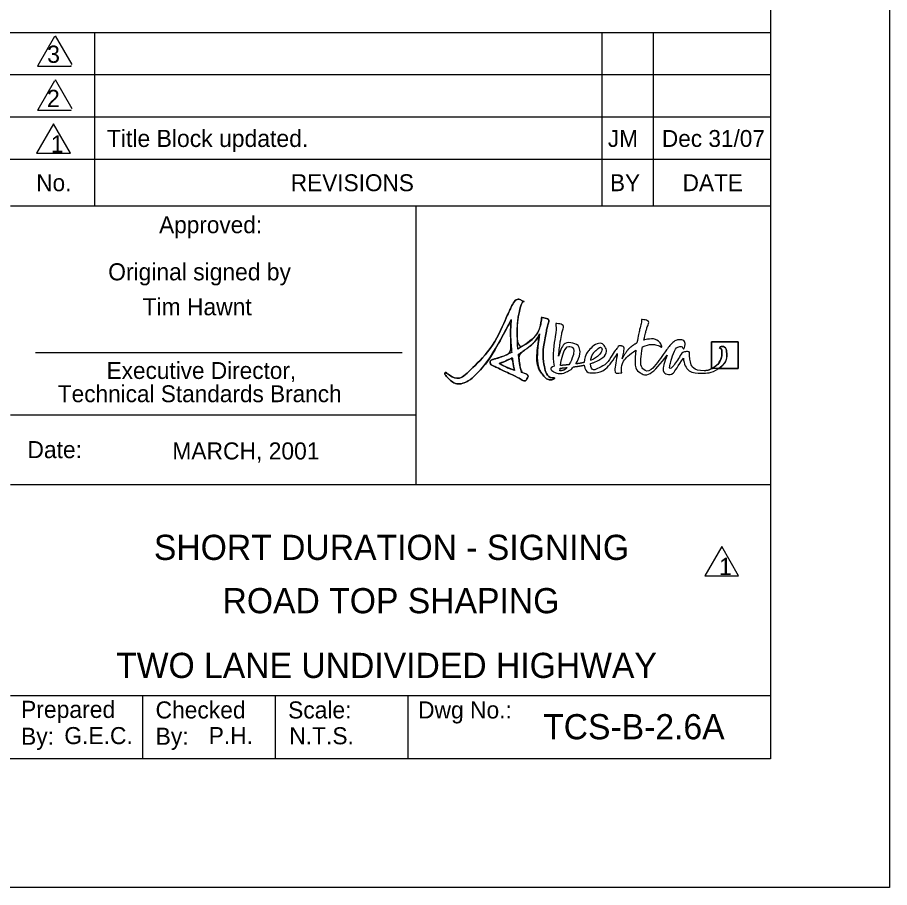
# Model space of a CAD drawing. Extents: x 1342 to 1558, y 178 to 457.
# Drawn here: x 1485 to 1558.3, y 177.9 to 251 of the extents above; entities that cross this region are included whole.
import ezdxf

# ---------------------------------------------------------------- set-up
doc = ezdxf.new("R2010")
doc.units = 0
for name, color, linetype in [('Level 1', 7, 'Continuous'), ('Level 10', 7, 'Continuous'), ('Level 2', 7, 'Continuous'), ('Level 22', 7, 'Continuous'), ('Level 44', 7, 'Continuous'), ('Level 45', 7, 'Continuous'), ('Level 53', 7, 'Continuous'), ('Level 60', 7, 'Continuous'), ('Level 63', 7, 'Continuous'), ('Level 7', 7, 'Continuous')]:
    doc.layers.add(name, color=color, linetype=linetype)

msp = doc.modelspace()

# ---------------------------------------------------------------- linework, layer by layer
at = {"layer": 'Level 1'}
for p, q in [((1518.49, 235.196), (1518.49, 211.787)), ((1484.439, 217.639), (1518.49, 217.639)), ((1484.439, 211.787), (1548.282, 211.787)), ((1484.439, 194.053), (1548.282, 194.053)), ((1495.57, 188.732), (1495.57, 194.053)), ((1506.7, 188.732), (1506.7, 194.053)), ((1517.83, 194.053), (1517.83, 188.732))]:
    msp.add_line(p, q, dxfattribs=at)
msp.add_lwpolyline([(1544.184, 206.591), (1542.765, 204.121), (1545.603, 204.121)], close=True, dxfattribs=at)
at = {"layer": 'Level 10'}
msp.add_line((1548.282, 188.732), (1548.282, 188.732), dxfattribs=at)
msp.add_line((1548.282, 188.732), (1548.282, 188.732), dxfattribs=at)
msp.add_line((1548.282, 188.732), (1548.282, 188.732), dxfattribs=at)
at = {"layer": 'Level 2'}
msp.add_line((1518.49, 235.196), (1518.49, 235.196), dxfattribs=at)
at = {"layer": 'Level 22'}
msp.add_line((1499.902, 188.732), (1499.902, 188.732), dxfattribs=at)
at = {"layer": 'Level 44'}
for p, q in [((1548.312, 249.746), (1484.432, 249.746)), ((1548.312, 246.197), (1484.432, 246.197)), ((1548.312, 242.648), (1484.432, 242.648)), ((1548.312, 239.1), (1484.432, 239.1)), ((1484.439, 235.196), (1548.312, 235.196))]:
    msp.add_line(p, q, dxfattribs=at)
msp.add_lwpolyline([(1488.059, 242.081), (1486.64, 239.611), (1489.478, 239.611)], close=True, dxfattribs=at)
at = {"layer": 'Level 45'}
msp.add_line((1518.505, 235.196), (1518.505, 235.196), dxfattribs=at)
at = {"layer": 'Level 53'}
msp.add_line((1543.939, 221.545), (1543.389, 221.545), dxfattribs=at)
msp.add_lwpolyline([(1543.939, 221.545), (1545.555, 221.545), (1545.555, 223.775), (1543.325, 223.775), (1543.325, 221.545), (1543.389, 221.545)], dxfattribs=at)
for points, degree in [([(1529.954, 220.736), (1529.714, 220.771), (1529.4, 221.098), (1529.305, 221.635), (1529.133, 222.601), (1529.235, 223.555), (1529.519, 224.976), (1529.573, 225.245), (1529.756, 225.711), (1529.173, 225.8), (1528.987, 225.829), (1529.083, 225.738), (1529.031, 225.492), (1528.807, 224.433), (1527.941, 223.671), (1527.072, 223.159), (1526.981, 224.371), (1527.019, 225.717), (1527.247, 226.542), (1527.439, 227.238), (1527.668, 227.11), (1527.384, 227.256), (1527.085, 227.411), (1526.764, 227.207), (1526.505, 226.688), (1526.245, 226.17), (1525.048, 223.354), (1523.137, 221.453), (1522.159, 220.481), (1521.274, 220.981), (1521.097, 221.131), (1520.953, 221.253), (1520.899, 221.065), (1521.078, 220.872), (1521.869, 220.02), (1523.025, 220.509), (1523.446, 220.929), (1524.608, 222.092), (1525.96, 224.594), (1526.507, 225.656), (1526.457, 225.058), (1526.44, 224.055), (1526.551, 222.88), (1525.959, 222.592), (1525.429, 222.422), (1525.179, 222.357), (1524.908, 222.286), (1524.74, 222.175), (1524.735, 222.049), (1524.729, 221.912), (1524.912, 221.796), (1525.175, 221.671), (1525.643, 221.449), (1527.015, 220.801), (1527.353, 220.604), (1527.642, 220.436), (1527.784, 220.567), (1527.87, 220.748), (1527.982, 220.985), (1527.674, 221.121), (1527.377, 221.21), (1527.262, 221.608), (1527.171, 222.144), (1527.11, 222.733), (1527.807, 223.163), (1528.494, 223.734), (1528.89, 224.449), (1528.79, 223.852), (1528.535, 221.821), (1529.175, 220.963), (1529.317, 220.774), (1529.629, 220.567), (1529.933, 220.597), (1530.076, 220.612), (1530.149, 220.706), (1530.134, 220.735), (1530.12, 220.765), (1530.038, 220.723), (1529.954, 220.736)], 3), ([(1527.072, 223.159), (1526.981, 224.371), (1527.019, 225.717), (1527.247, 226.542), (1527.439, 227.238), (1527.668, 227.11), (1527.384, 227.256), (1527.085, 227.411), (1526.764, 227.207), (1526.505, 226.688), (1526.245, 226.17), (1525.048, 223.354), (1523.137, 221.453), (1522.159, 220.481), (1521.274, 220.981), (1521.097, 221.131), (1520.953, 221.253), (1520.899, 221.065), (1521.078, 220.872), (1521.869, 220.02), (1523.025, 220.509), (1523.446, 220.929), (1524.608, 222.092), (1525.96, 224.594), (1526.507, 225.656)], 3), ([(1526.507, 225.656), (1526.457, 225.058), (1526.44, 224.055), (1526.551, 222.88)], 2), ([(1529.954, 220.736), (1529.714, 220.771), (1529.4, 221.098), (1529.305, 221.635), (1529.133, 222.601), (1529.235, 223.555), (1529.519, 224.976), (1529.573, 225.245), (1529.756, 225.711), (1529.173, 225.8), (1528.987, 225.829), (1529.083, 225.738), (1529.031, 225.492), (1528.807, 224.433), (1527.941, 223.671), (1527.072, 223.159)], 3), ([(1537.645, 223.918), (1537.71, 224.216), (1537.785, 224.518), (1537.867, 224.812), (1537.942, 225.081), (1538.163, 225.546), (1537.587, 225.636), (1537.404, 225.665), (1537.481, 225.576), (1537.421, 225.327), (1537.309, 224.87), (1537.169, 224.277), (1537.067, 223.682)], 3), ([(1530.49, 222.578), (1530.537, 223.146), (1530.628, 223.839), (1530.756, 224.481), (1530.81, 224.75), (1530.994, 225.216), (1530.41, 225.306), (1530.224, 225.334), (1530.253, 225.248), (1530.268, 224.997), (1530.289, 224.66), (1529.916, 222.621), (1530.111, 221.725)], 3), ([(1527.11, 222.733), (1527.807, 223.163), (1528.494, 223.734), (1528.89, 224.449)], 2), ([(1528.89, 224.449), (1528.79, 223.852), (1528.535, 221.821), (1529.175, 220.963), (1529.317, 220.774), (1529.629, 220.567), (1529.933, 220.597), (1530.076, 220.612), (1530.149, 220.706), (1530.134, 220.735), (1530.12, 220.765), (1530.038, 220.723), (1529.954, 220.736)], 3), ([(1531.928, 221.916), (1532.343, 222.589), (1532.307, 223.499), (1531.701, 223.652), (1530.997, 223.83), (1530.641, 223.146), (1530.49, 222.578)], 3), ([(1530.641, 221.787), (1530.735, 222.503), (1531.108, 223.498), (1531.572, 223.338), (1531.839, 223.245), (1531.698, 222.407), (1531.356, 221.85)], 3), ([(1533.154, 221.939), (1533.251, 221.968), (1533.337, 221.999), (1533.409, 222.031), (1534.292, 222.422), (1534.596, 223.012), (1534.371, 223.372), (1534.158, 223.713), (1533.55, 223.61), (1533.069, 223.103), (1532.832, 222.854), (1532.65, 222.425), (1532.628, 222.034)], 3), ([(1535.829, 222.353), (1535.885, 222.63), (1535.972, 222.936), (1535.978, 223.142), (1535.984, 223.359), (1535.835, 223.408), (1535.777, 223.424), (1535.651, 223.461), (1535.498, 223.398), (1535.347, 223.185), (1534.994, 222.688), (1534.547, 221.9), (1533.867, 221.57), (1533.38, 221.333), (1533.166, 221.572), (1533.154, 221.939)], 3), ([(1537.067, 223.682), (1536.593, 223.409), (1536.152, 222.953), (1535.829, 222.353)], 2), ([(1542.7, 221.347), (1541.784, 221.347), (1541.548, 222.059), (1541.504, 222.411), (1541.474, 222.645), (1541.525, 222.984), (1541.12, 222.939), (1540.837, 222.907), (1540.581, 222.356), (1540.223, 221.892), (1539.914, 221.493), (1539.777, 221.531), (1539.848, 221.873), (1539.938, 222.302), (1540.295, 223.307), (1540.704, 223.38), (1540.893, 223.414), (1540.961, 223.082), (1541.048, 223.29), (1541.135, 223.498), (1541.055, 223.948), (1540.632, 223.948), (1540.335, 223.948), (1539.98, 223.634), (1539.688, 223.276), (1539.434, 222.964), (1538.148, 221.072), (1537.609, 221.48), (1537.357, 221.671), (1537.378, 222.448), (1537.536, 223.365)], 3), ([(1537.536, 223.365), (1538.176, 223.611), (1538.708, 223.531), (1539.009, 223.386), (1539.157, 223.315), (1539.178, 223.325), (1539.114, 223.489), (1539.021, 223.729), (1538.506, 224.104), (1537.702, 223.932), (1537.683, 223.928), (1537.664, 223.923), (1537.645, 223.918)], 3), ([(1543.325, 223.775), (1543.325, 223.775), (1543.325, 221.545), (1543.325, 221.545), (1543.325, 221.545), (1543.389, 221.545), (1543.389, 221.545), (1543.873, 221.835), (1544.199, 222.389), (1544.198, 222.845), (1544.198, 223.239), (1543.989, 223.219), (1544.012, 223.274), (1544.08, 223.432), (1544.573, 223.342), (1544.602, 222.786), (1544.626, 222.314), (1544.379, 221.857), (1543.939, 221.545), (1543.939, 221.545), (1545.555, 221.545), (1545.555, 221.545), (1545.555, 221.545), (1545.555, 223.775), (1545.555, 223.775), (1545.555, 223.775), (1543.325, 223.775), (1543.325, 223.775)], 3), ([(1526.551, 222.88), (1525.959, 222.592), (1525.429, 222.422), (1525.179, 222.357), (1524.908, 222.286), (1524.74, 222.175), (1524.735, 222.049), (1524.729, 221.912), (1524.912, 221.796), (1525.175, 221.671), (1525.643, 221.449), (1527.015, 220.801), (1527.353, 220.604), (1527.642, 220.436), (1527.784, 220.567), (1527.87, 220.748), (1527.982, 220.985), (1527.674, 221.121), (1527.377, 221.21)], 3), ([(1527.377, 221.21), (1527.262, 221.608), (1527.171, 222.144), (1527.11, 222.733)], 2), ([(1532.635, 221.813), (1532.683, 221.421), (1532.94, 221.12), (1533.535, 221.175), (1534.381, 221.254), (1535.133, 222.293), (1535.417, 222.794)], 3), ([(1533.627, 223.058), (1533.923, 223.333), (1534.069, 223.313), (1534.108, 223.239), (1534.192, 223.08), (1533.844, 222.517), (1533.177, 222.209)], 3), ([(1533.177, 222.209), (1533.234, 222.512), (1533.394, 222.842), (1533.627, 223.058)], 2), ([(1535.417, 222.794), (1535.365, 222.257), (1535.016, 221.085), (1535.612, 221.145), (1535.845, 221.169), (1535.744, 221.206), (1535.758, 221.408), (1535.809, 222.114), (1536.398, 222.713), (1536.98, 223.08)], 3), ([(1536.98, 223.08), (1536.879, 222.215), (1536.914, 221.442), (1537.306, 221.197), (1538.028, 220.745), (1539.051, 221.934), (1539.614, 222.661)], 3), ([(1543.389, 221.545), (1543.873, 221.835), (1544.199, 222.389), (1544.198, 222.845), (1544.198, 223.239), (1543.989, 223.219), (1544.012, 223.274), (1544.08, 223.432), (1544.573, 223.342), (1544.602, 222.786), (1544.626, 222.314), (1544.379, 221.857), (1543.939, 221.545)], 3), ([(1525.482, 221.948), (1525.791, 222.061), (1526.184, 222.226), (1526.598, 222.443)], 2), ([(1525.482, 221.948), (1525.791, 222.061), (1526.184, 222.226), (1526.598, 222.443), (1526.654, 221.97), (1526.714, 221.627), (1526.782, 221.374), (1526.479, 221.483), (1526.046, 221.66), (1525.482, 221.948)], 3), ([(1526.782, 221.374), (1526.479, 221.483), (1526.046, 221.66), (1525.482, 221.948)], 2), ([(1526.598, 222.443), (1526.654, 221.97), (1526.714, 221.627), (1526.782, 221.374)], 2), ([(1532.628, 222.034), (1532.425, 221.99), (1532.19, 221.951), (1531.928, 221.916)], 2), ([(1539.614, 222.661), (1539.327, 222.015), (1539.165, 221.188), (1539.595, 221.062), (1540.1, 220.914), (1540.498, 221.752), (1540.964, 222.393)], 3), ([(1540.964, 222.393), (1541.018, 221.933), (1541.325, 221.14), (1542.561, 221.14), (1543.117, 221.14), (1543.589, 221.297), (1543.939, 221.545)], 3), ([(1530.111, 221.725), (1529.86, 221.643), (1529.758, 221.455), (1530.081, 221.255), (1530.303, 221.118), (1530.793, 221.072), (1531.288, 221.316), (1531.466, 221.404), (1531.62, 221.527), (1531.748, 221.672)], 3), ([(1530.566, 221.355), (1530.598, 221.382), (1530.617, 221.422), (1530.617, 221.47), (1530.618, 221.5), (1530.618, 221.532), (1530.62, 221.565)], 3), ([(1530.767, 221.356), (1530.686, 221.344), (1530.619, 221.345), (1530.566, 221.355)], 2), ([(1530.62, 221.565), (1530.746, 221.571), (1530.942, 221.585), (1531.177, 221.608)], 2), ([(1531.356, 221.85), (1531.131, 221.827), (1530.892, 221.806), (1530.641, 221.787)], 2), ([(1531.177, 221.608), (1531.054, 221.473), (1530.916, 221.379), (1530.767, 221.356)], 2), ([(1531.748, 221.672), (1532.043, 221.71), (1532.352, 221.757), (1532.635, 221.813)], 2), ([(1543.389, 221.545), (1543.183, 221.423), (1542.949, 221.347), (1542.7, 221.347)], 2)]:
    msp.add_open_spline(points, degree=degree, dxfattribs=at)
at = {"layer": 'Level 60'}
for p, q in [((1548.282, 188.732), (1548.282, 188.732)), ((1558.282, 177.923), (1558.282, 177.923))]:
    msp.add_line(p, q, dxfattribs=at)
for points in [[(1342.282, 456.923), (1558.282, 456.923), (1558.282, 177.923), (1342.282, 177.923)], [(1361.408, 446.114), (1548.282, 446.114), (1548.282, 188.732), (1361.408, 188.732)]]:
    msp.add_lwpolyline(points, close=True, dxfattribs=at)
at = {"layer": 'Level 63'}
for p, q in [((1491.529, 243.274), (1491.529, 249.746)), ((1534.118, 249.746), (1534.118, 235.196)), ((1538.429, 249.746), (1538.429, 235.196)), ((1491.529, 235.196), (1491.529, 243.274))]:
    msp.add_line(p, q, dxfattribs=at)
for points in [[(1488.138, 249.415), (1486.745, 246.99)], [(1489.62, 247.067), (1488.226, 249.492)], [(1486.745, 246.99), (1486.719, 246.945), (1489.558, 246.945), (1489.532, 246.99)], [(1488.138, 245.699), (1486.745, 243.274)], [(1489.62, 243.351), (1488.226, 245.776)], [(1486.745, 243.274), (1486.719, 243.229), (1489.558, 243.229), (1489.532, 243.274)]]:
    msp.add_lwpolyline(points, dxfattribs=at)
at = {"layer": 'Level 7'}
msp.add_line((1486.547, 222.882), (1517.348, 222.882), dxfattribs=at)

# ---------------------------------------------------------------- texts
at = {"layer": 'Level 1'}
for s, height, p in [('Title Block updated. ', 1.44, (1492.548, 240.144)), ('Date:', 1.4329, (1485.873, 214.001)), ('1', 1.448, (1543.957, 204.178)), ('Prepared', 1.44, (1485.327, 192.173)), ('Checked', 1.4329, (1496.633, 192.131)), ('Scale:', 1.4329, (1507.763, 192.131)), ('Dwg No.:', 1.4329, (1518.681, 192.131)), ('By:', 1.44, (1485.327, 189.917)), ('By:', 1.44, (1496.633, 189.917)), ('    N.T.S.   ', 1.43292, (1505.734, 189.96))]:
    msp.add_text(s, height=height, rotation=360, dxfattribs=at).set_placement(p)
at = {"layer": 'Level 10'}
for s, height, p in [('SHORT DURATION - SIGNING', 2.115, (1496.493, 205.449)), ('ROAD TOP SHAPING', 2.11517, (1502.259, 200.97)), ('TWO LANE UNDIVIDED HIGHWAY', 2.11517, (1493.323, 195.532))]:
    msp.add_text(s, height=height, rotation=359.99999, dxfattribs=at).set_placement(p)
at = {"layer": 'Level 44'}
for s, height, p in [('3', 1.448, (1487.528, 247.214)), ('2', 1.448, (1487.511, 243.498)), ('1', 1.448, (1487.832, 239.668)), ('JM', 1.4189, (1534.622, 240.149)), ('Dec 31/07', 1.419, (1539.163, 240.149)), ('No.', 1.4195, (1486.611, 236.431)), ('REVISIONS', 1.4195, (1507.994, 236.431)), ('BY', 1.4195, (1534.8, 236.431)), ('DATE', 1.4194, (1540.902, 236.431))]:
    msp.add_text(s, height=height, rotation=360, dxfattribs=at).set_placement(p)
at = {"layer": 'Level 60'}
for s, height, p in [('MARCH, 2001', 1.434, (1498.039, 213.89)), ('TCS-B-2.6A', 2.115, (1529.185, 190.38))]:
    msp.add_text(s, height=height, dxfattribs=at).set_placement(p)
for s, p in [('G.E.C.', (1488.97, 189.974)), ('P.H.', (1501.092, 189.974))]:
    msp.add_text(s, height=1.433, rotation=360, dxfattribs=at).set_placement(p)
at = {"layer": 'Level 7'}
for s, height, p in [('Approved:', 1.4187, (1496.933, 232.902)), ('Original signed by', 1.434, (1492.655, 228.939)), ('Tim Hawnt', 1.434, (1495.545, 226.005)), ('Executive Director,', 1.41872, (1492.522, 220.655)), ('Technical Standards Branch', 1.41872, (1488.427, 218.703))]:
    msp.add_text(s, height=height, dxfattribs=at).set_placement(p)

doc.saveas('drawing.dxf')
